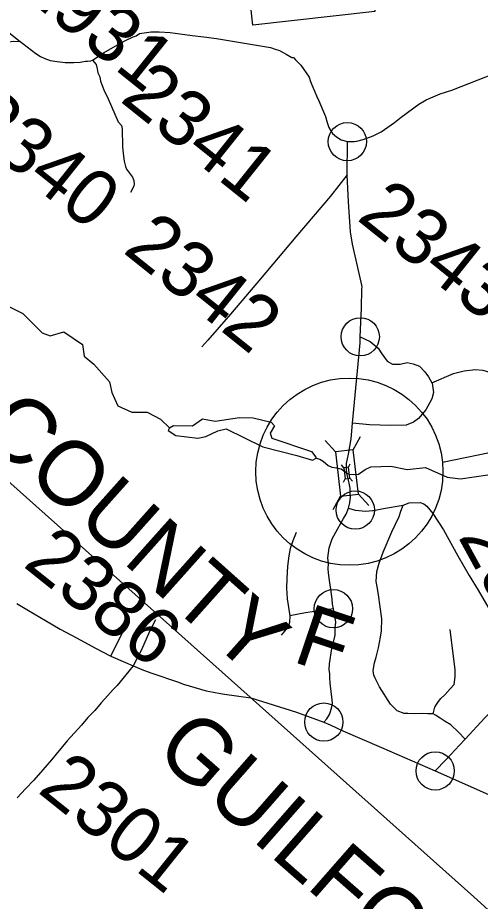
# Model space of a CAD drawing. Extents: x 1732765 to 1738218, y 913652 to 917906.
# Drawn here: x 1734415.9 to 1734585.5, y 916756.7 to 917080.6 of the extents above; entities that cross this region are included whole.
import ezdxf

# ---------------------------------------------------------------- set-up
doc = ezdxf.new("R2010")
doc.units = 0
for name, color, linetype in [('Old_Level_23', 7, 'Continuous'), ('Old_Level_24', 7, 'Continuous'), ('Old_Level_28', 7, 'Continuous'), ('Old_Level_29', 7, 'Continuous'), ('Old_Level_32', 7, 'Continuous'), ('Old_Level_50', 7, 'Continuous'), ('Old_Level_52', 7, 'Continuous'), ('Old_Level_56', 7, 'Continuous'), ('Old_Level_59', 7, 'Continuous'), ('Old_Level_60', 7, 'Continuous'), ('Old_Level_8', 7, 'Continuous'), ('Old_Level_9', 7, 'Continuous')]:
    doc.layers.add(name, color=color, linetype=linetype)

msp = doc.modelspace()

# ---------------------------------------------------------------- linework, layer by layer
at = {"layer": 'Old_Level_24'}
msp.add_line((1734571.6, 916917.59), (1734650.42, 916934.01), dxfattribs=at)
for centre, radius in [((1734536.72, 917035.12), 7.01), ((1734541.44, 916963.59), 7.01), ((1734537.47, 916914.17), 34.3), ((1734539.62, 916900.09), 7.01), ((1734531.59, 916863.93), 7.01), ((1734528.09, 916822.38), 7.01), ((1734568.91, 916804.48), 7.01)]:
    msp.add_circle(centre, radius, dxfattribs=at)
at = {"layer": 'Old_Level_28'}
msp.add_line((1734568.91, 916804.48), (1734589.55, 916795.35), dxfattribs=at)
for points in [[(1734415.51, 916865.88), (1734419.87, 916863.29), (1734426.07, 916859.6), (1734431.45, 916856.5), (1734437.73, 916853.18), (1734444.1, 916849.66), (1734450.07, 916846.53)], [(1734450.07, 916846.53), (1734455.33, 916844.26), (1734458.22, 916843.02)], [(1734458.22, 916843.02), (1734461.95, 916841.43), (1734465.1, 916840.27), (1734474.47, 916837.1), (1734476.7, 916836.33), (1734484.95, 916833.87), (1734487.65, 916833.41), (1734490.18, 916832.9), (1734491.67, 916832.58), (1734501.35, 916831.32)], [(1734501.35, 916831.32), (1734518.08, 916826.01), (1734528.09, 916822.38)], [(1734528.09, 916822.38), (1734530.37, 916821.34), (1734535.06, 916819.23), (1734549.21, 916813.07), (1734568.91, 916804.48)]]:
    msp.add_lwpolyline(points, dxfattribs=at)
at = {"layer": 'Old_Level_29'}
msp.add_line((1734405.57, 917080.66), (1734416.76, 917071.8), dxfattribs=at)
for points in [[(1734443.29, 917065.01), (1734447.62, 917067.74), (1734452.41, 917070.54), (1734455.34, 917072.19), (1734458.18, 917073.57), (1734459.31, 917073.95), (1734460.46, 917074.71), (1734464.79, 917075.32), (1734467.79, 917075.3), (1734471.82, 917075.09), (1734477.12, 917074.41), (1734479.85, 917074.05), (1734484.07, 917073.51), (1734488.76, 917072.86), (1734508.52, 917069.57), (1734510.2, 917069.05), (1734511.84, 917068.47), (1734513, 917067.85), (1734514.24, 917067.15), (1734516.32, 917065.98), (1734517.03, 917065.91), (1734517.75, 917065.14), (1734519.67, 917063.17), (1734522.76, 917058.72), (1734523.24, 917057.15), (1734523.7, 917055.91), (1734524.85, 917053.34), (1734525.46, 917051.96), (1734526.31, 917050.03), (1734528.65, 917044.27), (1734529.37, 917042.08), (1734529.97, 917040.34), (1734530.8, 917038.86), (1734531.32, 917038.11), (1734531.95, 917037.48), (1734532.71, 917036.87), (1734534.47, 917035.83), (1734536.72, 917035.12)], [(1734416.76, 917071.8), (1734417.8, 917071.06), (1734422.55, 917067.47), (1734424.2, 917066.32), (1734425.82, 917065.55), (1734427.83, 917064.86), (1734430.36, 917064.48), (1734433.29, 917064.15), (1734436.44, 917064.09), (1734438.76, 917064.25), (1734440.7, 917064.62), (1734441.46, 917064.55), (1734442.66, 917064.79), (1734443.29, 917065.01)], [(1734536.72, 917035.12), (1734538.44, 917035.11), (1734539.32, 917035.17), (1734540.23, 917035.33), (1734542.52, 917035.92), (1734546.21, 917037.3), (1734549.05, 917038.66), (1734553.95, 917042.13), (1734556.42, 917044.07), (1734562.96, 917048.87), (1734565.61, 917050.38), (1734570.74, 917052.63), (1734575.04, 917054.01), (1734578.44, 917055.38), (1734587.51, 917058.83), (1734592.31, 917060.75), (1734593.57, 917061.32)]]:
    msp.add_lwpolyline(points, dxfattribs=at)
at = {"layer": 'Old_Level_32'}
msp.add_line((1734536.61, 917022.94), (1734536.72, 917035.12), dxfattribs=at)
for points in [[(1734366.02, 917011.91), (1734370.52, 917018.1), (1734374.3, 917022.95), (1734376.65, 917026.13), (1734379.3, 917029.47), (1734388.2, 917041.16), (1734411.73, 917071.35), (1734412.51, 917071.64), (1734413.46, 917071.79), (1734414.36, 917071.89), (1734416.76, 917071.8)], [(1734443.29, 917065.01), (1734444.69, 917063.34), (1734444.97, 917061.74), (1734445.23, 917060.35), (1734446.01, 917058.81), (1734446.28, 917057.22), (1734447.39, 917054.15), (1734448.98, 917050.77), (1734452.75, 917042.36), (1734453.96, 917041.04), (1734454.13, 917039.74), (1734454.33, 917033.36), (1734454.52, 917030.74), (1734454.87, 917027.94), (1734455.38, 917026.04), (1734455.81, 917024.98), (1734457.9, 917022.08), (1734458.48, 917020.83), (1734458.58, 917019.53), (1734458.42, 917018.94), (1734457.95, 917017.87), (1734457.19, 917016.45)], [(1734536.61, 917022.94), (1734530.55, 917015.18), (1734517.78, 917000.18), (1734504.91, 916984.82), (1734493.84, 916971.93), (1734485.55, 916962.41), (1734483.36, 916959.89)], [(1734541.44, 916963.59), (1734541.84, 916974.07), (1734542.08, 916981.15), (1734542.12, 916981.89), (1734542.06, 916982.49), (1734540.51, 916988.99), (1734538.63, 916997.53), (1734537.88, 917002.07), (1734537.13, 917013.05), (1734536.61, 917022.94)], [(1734538.65, 916931.96), (1734541.35, 916961.44), (1734541.44, 916963.59)], [(1734541.44, 916963.59), (1734545.13, 916961.9), (1734547.98, 916959.38), (1734549.36, 916957.35), (1734551.34, 916954.61), (1734553.25, 916953.54), (1734556.08, 916953.6), (1734558.59, 916954.13), (1734560.82, 916953.74), (1734563.1, 916952.83), (1734565.13, 916950.74), (1734566.49, 916948.97), (1734567.69, 916946.72)], [(1734567.69, 916946.72), (1734575.63, 916950.11), (1734579.54, 916951.12), (1734583.51, 916951.56), (1734586.42, 916951.31), (1734590.94, 916950.05)], [(1734567.69, 916946.72), (1734567.79, 916946.54), (1734568.29, 916943.12), (1734567.64, 916940.87), (1734565.53, 916936.78), (1734562.79, 916933.64), (1734561.01, 916932.29), (1734558.3, 916931.22), (1734552.66, 916931.11), (1734544.78, 916931.39), (1734538.65, 916931.96)], [(1734536.54, 916913.67), (1734536.39, 916915.01), (1734536.41, 916917.17), (1734537.14, 916920.57), (1734537.67, 916923.35), (1734538.12, 916926.17), (1734538.65, 916931.96)], [(1734537.18, 916900.8), (1734537.63, 916902.74), (1734537.87, 916905), (1734537.79, 916906.54), (1734537.69, 916908.07), (1734537.49, 916909.33), (1734537.08, 916911.05), (1734536.54, 916913.67)], [(1734537.18, 916900.8), (1734539.62, 916900.09), (1734543.48, 916899.67), (1734545.93, 916899.92), (1734546.34, 916899.99), (1734549.94, 916900.63), (1734557.13, 916901.85)], [(1734568.17, 916825.38), (1734566.22, 916825.45), (1734564.34, 916825.59), (1734561.45, 916825.41), (1734558.83, 916825.5), (1734557.51, 916825.59), (1734554.93, 916826.56), (1734552.52, 916828.93), (1734548.46, 916835.34), (1734546.85, 916838.53), (1734546.42, 916839.56), (1734546.23, 916841.3), (1734546.67, 916844.12), (1734547.3, 916846.2), (1734548.1, 916849.61), (1734548.91, 916853.46), (1734549.24, 916855.86), (1734549.3, 916860.18), (1734548.13, 916869.08), (1734547.81, 916871.38), (1734547.28, 916873.9), (1734547.48, 916877.55), (1734548.36, 916880.64), (1734549.87, 916884.63), (1734552.98, 916892.06), (1734555.66, 916897.75), (1734556.36, 916899.69), (1734557.13, 916901.85)], [(1734557.13, 916901.85), (1734559.39, 916902.75), (1734563.39, 916902.9), (1734564.76, 916902.32), (1734565.82, 916901.47), (1734566.94, 916900.14), (1734568, 916898.85), (1734572.01, 916892.86), (1734577.2, 916883.33), (1734581.37, 916876.09), (1734584.66, 916870.7), (1734588.62, 916864.02), (1734590.63, 916861.08), (1734592.68, 916858.77), (1734597.29, 916854.8), (1734602.46, 916850.57), (1734608.43, 916845.69)], [(1734531.59, 916863.93), (1734531.32, 916865.56), (1734531.1, 916867.45), (1734530.6, 916871.09), (1734530.12, 916874.22), (1734529.85, 916877.11), (1734529.68, 916878.57), (1734529.75, 916880.51), (1734529.56, 916882.57), (1734530.03, 916886.28), (1734531.19, 916889.6), (1734533.16, 916893.1), (1734535.36, 916896.97), (1734536.28, 916898.62), (1734537.18, 916900.8)], [(1734517.99, 916891.82), (1734516.72, 916888.82), (1734515.71, 916885.99), (1734515.31, 916883.3), (1734514.82, 916879.55), (1734514.56, 916874.99), (1734514.39, 916871.48), (1734514.62, 916867.54), (1734515.58, 916861.37)], [(1734531.59, 916863.93), (1734527.98, 916863.37), (1734521.32, 916862.42), (1734515.58, 916861.37)], [(1734528.09, 916822.38), (1734529.13, 916823.55), (1734530.11, 916825.22), (1734530.5, 916826.21), (1734531.02, 916827.97), (1734531.21, 916829.23), (1734531.14, 916830.57), (1734530.44, 916836.68), (1734530.28, 916838.55), (1734530.26, 916840.02), (1734530.08, 916841.67), (1734530.17, 916843.76), (1734531.08, 916849.36), (1734532.22, 916854.11), (1734532.23, 916856.93), (1734532.46, 916858.99), (1734532.19, 916860.62), (1734531.9, 916862.44), (1734531.59, 916863.93)], [(1734450.07, 916846.53), (1734453.23, 916853.02), (1734455.33, 916857.22), (1734456.8, 916860.47)], [(1734466.34, 916859.85), (1734464.19, 916855.58), (1734461.27, 916848.92), (1734458.22, 916843.02)], [(1734515.58, 916861.37), (1734515.51, 916858.92), (1734515.32, 916858.06), (1734514.91, 916857.39), (1734514.25, 916856.41), (1734512.48, 916854.19)], [(1734568.17, 916825.38), (1734568.82, 916827.85), (1734569.39, 916828.89), (1734570.11, 916829.9), (1734570.96, 916831.07), (1734572.42, 916832.42), (1734573.39, 916833.52), (1734574.38, 916834.58), (1734575.86, 916836.21), (1734576.01, 916837.06), (1734576.28, 916839.04), (1734576.21, 916841.48), (1734574.42, 916856.28)], [(1734579.89, 916816.09), (1734587.14, 916823.89), (1734594.56, 916831.52), (1734603.18, 916840.22), (1734604, 916840.9), (1734605.94, 916842.95), (1734606.71, 916843.64), (1734607.61, 916844.4), (1734608.43, 916845.69)], [(1734458.22, 916843.02), (1734452.31, 916835.83), (1734450.81, 916834.31), (1734448.95, 916832.11), (1734446.5, 916829.4), (1734444.09, 916826.66), (1734441.56, 916824.01), (1734439.32, 916821.31), (1734433.95, 916815.5), (1734428.23, 916808.59), (1734425.1, 916804.91), (1734421.74, 916801.1), (1734418.79, 916797.88), (1734415.7, 916794.68)], [(1734579.89, 916816.09), (1734577.41, 916818.66), (1734574.6, 916821.4), (1734572.51, 916822.66), (1734570.79, 916823.85), (1734568.99, 916824.91), (1734568.17, 916825.38)], [(1734568.91, 916804.48), (1734569.54, 916805.13), (1734572.17, 916807.89), (1734573.11, 916808.76), (1734577.79, 916813.91), (1734579.89, 916816.09)]]:
    msp.add_lwpolyline(points, dxfattribs=at)
at = {"layer": 'Old_Level_50'}
for p, q in [((1734532.31, 916921.43), (1734528.54, 916925.55)), ((1734538.82, 916922.2), (1734541.51, 916927.1)), ((1734535.48, 916915.61), (1734534.54, 916916.64)), ((1734537.11, 916915.8), (1734537.78, 916917.03)), ((1734535.29, 916910.31), (1734535.97, 916911.54)), ((1734538.54, 916910.7), (1734537.59, 916911.73)), ((1734531.56, 916900.24), (1734534.25, 916905.14)), ((1734544.53, 916901.79), (1734540.77, 916905.91))]:
    msp.add_line(p, q, dxfattribs=at)
msp.add_lwpolyline([(1734532.31, 916921.43), (1734534.25, 916905.14), (1734540.77, 916905.91), (1734538.82, 916922.2)], close=True, dxfattribs=at)
msp.add_lwpolyline([(1734535.48, 916915.61), (1734535.97, 916911.54), (1734537.59, 916911.73), (1734537.11, 916915.8), (1734535.48, 916915.61)], dxfattribs=at)
at = {"layer": 'Old_Level_52'}
msp.add_lwpolyline([(1734732.93, 916622.27), (1734723.88, 916630.49), (1734583.09, 916758.4), (1734358.65, 916958.62), (1734222.3, 917078.43)], dxfattribs=at)
at = {"layer": 'Old_Level_59'}
for points in [[(1734407.79, 916977.04), (1734417.78, 916972.12), (1734424.88, 916965.03), (1734427.79, 916963.99), (1734432.79, 916965.47), (1734439.65, 916960.72), (1734440.24, 916956.49), (1734443.82, 916953.6), (1734449.5, 916947.05), (1734450.34, 916943.14), (1734452.62, 916938.35), (1734457.71, 916936.03), (1734463.37, 916936.01), (1734468.2, 916933.37), (1734471.5, 916930.18)], [(1734525.25, 916919.13), (1734526.64, 916918.7), (1734527.83, 916917.96), (1734529.68, 916916.42), (1734531.06, 916915.77), (1734532.72, 916915.54), (1734534.5, 916915.16), (1734535.36, 916914.62), (1734536.54, 916913.67), (1734537.4, 916913.24), (1734539.11, 916913.07), (1734540.8, 916913.26), (1734543.23, 916914.9), (1734545.37, 916915.89), (1734552.6, 916916.17), (1734558.61, 916915), (1734565.36, 916915.67), (1734573.26, 916912.17), (1734578.13, 916911.53), (1734588.18, 916912.98)]]:
    msp.add_lwpolyline(points, dxfattribs=at)
at = {"layer": 'Old_Level_60'}
for points in [[(1734471.5, 916930.18), (1734473.01, 916931.06), (1734479.98, 916931.02), (1734483.58, 916933.47), (1734488.29, 916932.64), (1734497.18, 916933.98), (1734502.2, 916933.85), (1734508.76, 916932.33), (1734510.05, 916930.94), (1734508.39, 916928.26), (1734509.06, 916926.42), (1734523.63, 916921.53), (1734525.17, 916919.5), (1734525.25, 916919.13)], [(1734471.5, 916930.18), (1734470.99, 916929.22), (1734473.85, 916927.48), (1734481.94, 916926.5), (1734484.83, 916927.08), (1734489.24, 916929.17), (1734492.24, 916929.88), (1734505.67, 916923.26), (1734518.16, 916920.1), (1734523.93, 916918.37), (1734525.25, 916919.13)]]:
    msp.add_lwpolyline(points, dxfattribs=at)
at = {"layer": 'Old_Level_9'}
msp.add_lwpolyline([(1734497.14, 917122.49), (1734541.79, 917127.44), (1734546.74, 917082.79), (1734502.09, 917077.84)], close=True, dxfattribs=at)

# ---------------------------------------------------------------- texts
at = {"layer": 'Old_Level_23'}
for s, rotation, p in [('2931', 321.3297, (1734415.14, 917090.59)), ('2341', 321.3297, (1734452.96, 917050.17)), ('2340', 321.3297, (1734394.87, 917040.11)), ('2343', 321.3297, (1734539.74, 917006.75)), ('2342', 321.3297, (1734454.02, 916994.8)), ('2917', 298.7098, (1734577.09, 916890.38))]:
    msp.add_text(s, height=20.505, rotation=rotation, dxfattribs=at).set_placement(p)
at = {"layer": 'Old_Level_52'}
for s, rotation, p in [('ROCKINGHAM COUNTY', 318.2329, (1734231.18, 917080.08)), ('GUILFORD  COUNTY', 318.7217, (1734465.36, 916810.93))]:
    msp.add_text(s, height=23.786, rotation=rotation, dxfattribs=at).set_placement(p)
at = {"layer": 'Old_Level_56'}
msp.add_text('F', height=22.56, rotation=341.3297, dxfattribs=at).set_placement((1734516.1, 916844.71))
at = {"layer": 'Old_Level_8'}
for s, p in [('2386', (1734417.41, 916879.73)), ('2301', (1734422.74, 916796.95))]:
    msp.add_text(s, height=20.505, rotation=321.3297, dxfattribs=at).set_placement(p)

doc.saveas('drawing.dxf')
